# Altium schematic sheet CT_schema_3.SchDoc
size 136 x 123 mm
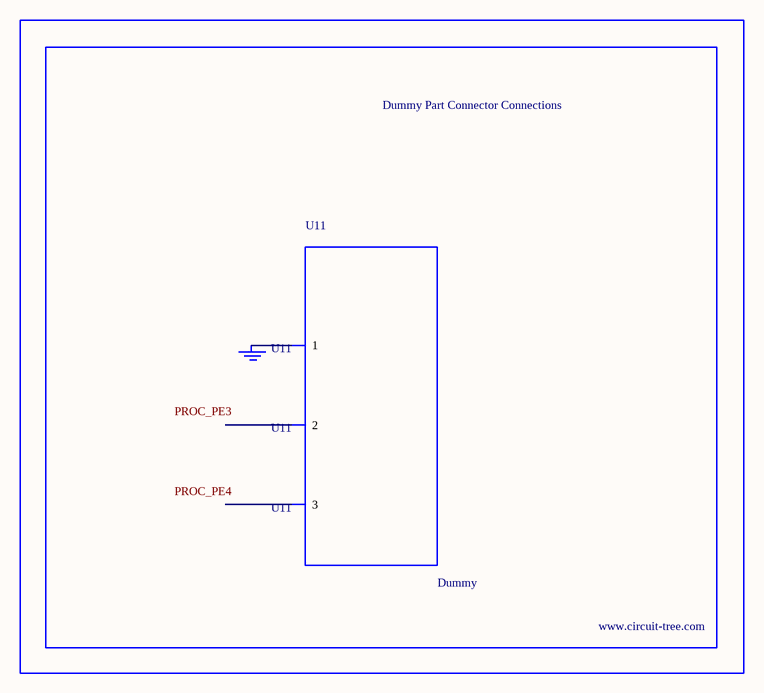
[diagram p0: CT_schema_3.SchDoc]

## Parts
BORDER2  (no value)
GND_INSTANCE_2_0  (no value)
U11  Dummy  [DUMMY_PACKAGE_111]

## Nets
NetGND_INSTANCE_2_0_0: GND_INSTANCE_2_0.0(GND) U11.1

Not connected (* = marked no-connect by the designer): U11 2 3

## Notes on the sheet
- Labels drawn without touching a wire or pin: PROC_PE3, PROC_PE4

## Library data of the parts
BORDER2 = BORDER_PAGE2
GND_INSTANCE_2_0 = GND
